(* Logix 5000 project; controller DNP3Master vendor 1 type 14 code 96 rev 19.13; software revision 19.01; part 3 of 5 *)

ADD_ON_INSTRUCTION PSDNP3EventG21V05   (* revision 1.0, vendor ProSoft Technology Inc *)
// Processes DNP3 Event and updates corresponding static DNP3 object. (Report by Exception.)
// G21V05 - Frozen Counter - 32bit with Status and Time
VAR_IN_OUT
   EventBuffer : PSDNP3MasterEvent[1]; {required}
END_VAR
VAR_INPUT
   BufferSize : DINT; {required}
   CurrentBufferIndex : DINT; {required}
   Reset : BOOL; {required}
   OutstationNodeAddress : INT; {required}
   OutstationIPAddress0 : INT; {required}
   OutstationIPAddress1 : INT; {required}
   OutstationIPAddress2 : INT; {required}
   OutstationIPAddress3 : INT; {required}
END_VAR
VAR_IN_OUT
   DNP3StaticObject : PSDNP3FrozenCounter32WithFlagTime[1]; {required}
END_VAR
VAR_INPUT
   MaxtElementCount : DINT; {required}
END_VAR
VAR_OUTPUT
   EventsProcessed : DINT; {access Read Only, visible}
   LastElementIndex : DINT; {access Read Only, visible}
   LastValue : DINT; {access Read Only, visible}
   LastStatus : SINT; {access Read Only, visible}
   CurrentUnloadIndex : DINT; {access Read Only, visible}
END_VAR
VAR
   UnloadIndex : DINT; {access None}
   EnableInTemp : BOOL; {access None}
   InitialScan : BOOL; {access None}
   EntryValidForProcessing : BOOL; {access None}
   ElementIndex : DINT; {access None}
   NextIndex : DINT; {access None}
   ResetPulse : BOOL; {access None}
   ResetONS : BOOL; {access None}
END_VAR

ROUTINE Logic   (* ladder *)
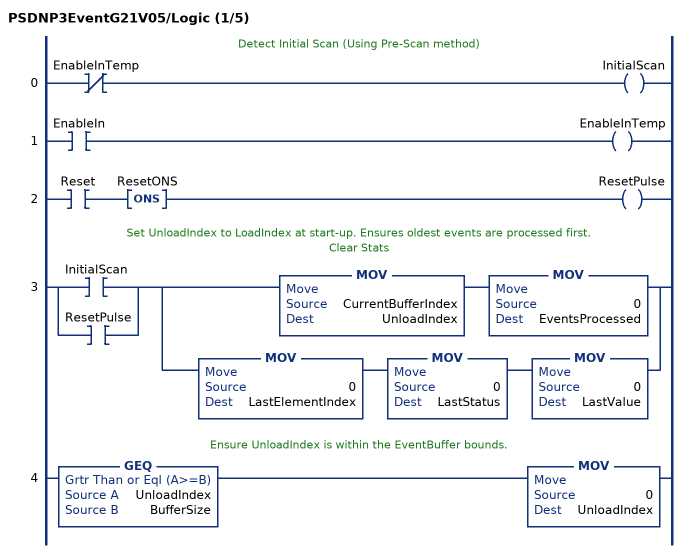
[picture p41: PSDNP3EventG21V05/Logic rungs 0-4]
   // Detect Initial Scan (Using Pre-Scan method)
   0: XIO(EnableInTemp)OTE(InitialScan);
   1: XIC(EnableIn)OTE(EnableInTemp);
   2: XIC(Reset)ONS(ResetONS)OTE(ResetPulse);
   // Set UnloadIndex to LoadIndex at start-up. Ensures oldest events are processed first.
   // Clear Stats
   3: [XIC(InitialScan) ,XIC(ResetPulse) ][MOV(CurrentBufferIndex,UnloadIndex) MOV(0,EventsProcessed) ,MOV(0,LastElementIndex) MOV(0,LastStatus) MOV(0,LastValue) ];
   // Ensure UnloadIndex is within the EventBuffer bounds.
   4: GEQ(UnloadIndex,BufferSize)MOV(0,UnloadIndex);
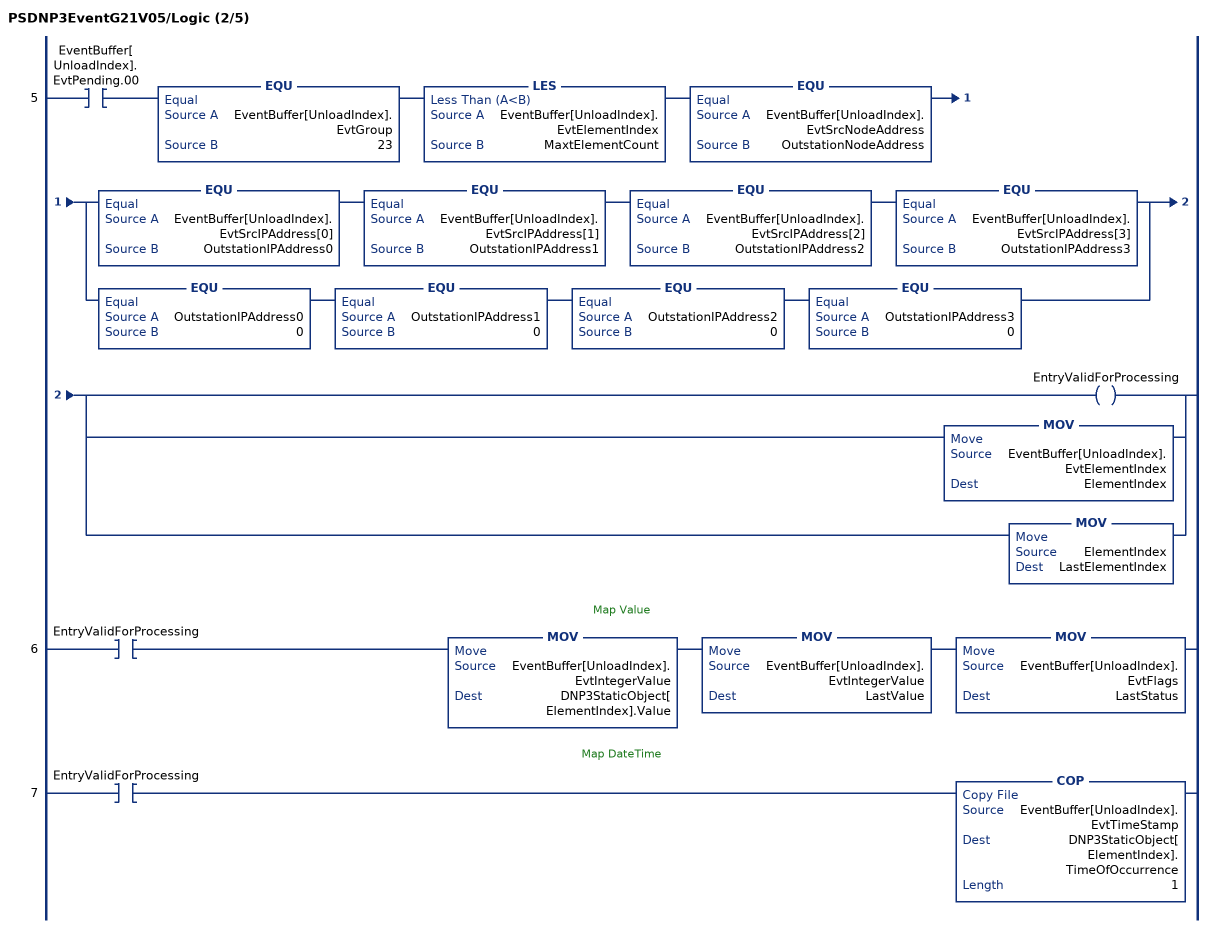
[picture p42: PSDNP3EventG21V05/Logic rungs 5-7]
   5: XIC(EventBuffer[UnloadIndex].EvtPending.00)EQU(EventBuffer[UnloadIndex].EvtGroup,23)LES(EventBuffer[UnloadIndex].EvtElementIndex,MaxtElementCount)EQU(EventBuffer[UnloadIndex].EvtSrcNodeAddress,OutstationNodeAddress)[EQU(EventBuffer[UnloadIndex].EvtSrcIPAddress[0],OutstationIPAddress0) EQU(EventBuffer[UnloadIndex].EvtSrcIPAddress[1],OutstationIPAddress1) EQU(EventBuffer[UnloadIndex].EvtSrcIPAddress[2],OutstationIPAddress2) EQU(EventBuffer[UnloadIndex].EvtSrcIPAddress[3],OutstationIPAddress3) ,EQU(OutstationIPAddress0,0) EQU(OutstationIPAddress1,0) EQU(OutstationIPAddress2,0) EQU(OutstationIPAddress3,0) ][OTE(EntryValidForProcessing) ,MOV(EventBuffer[UnloadIndex].EvtElementIndex,ElementIndex) ,MOV(ElementIndex,LastElementIndex) ];
   // Map Value
   6: XIC(EntryValidForProcessing)MOV(EventBuffer[UnloadIndex].EvtIntegerValue,DNP3StaticObject[ElementIndex].Value)MOV(EventBuffer[UnloadIndex].EvtIntegerValue,LastValue)MOV(EventBuffer[UnloadIndex].EvtFlags,LastStatus);
   // Map DateTime
   7: XIC(EntryValidForProcessing)COP(EventBuffer[UnloadIndex].EvtTimeStamp,DNP3StaticObject[ElementIndex].TimeOfOccurrence,1);
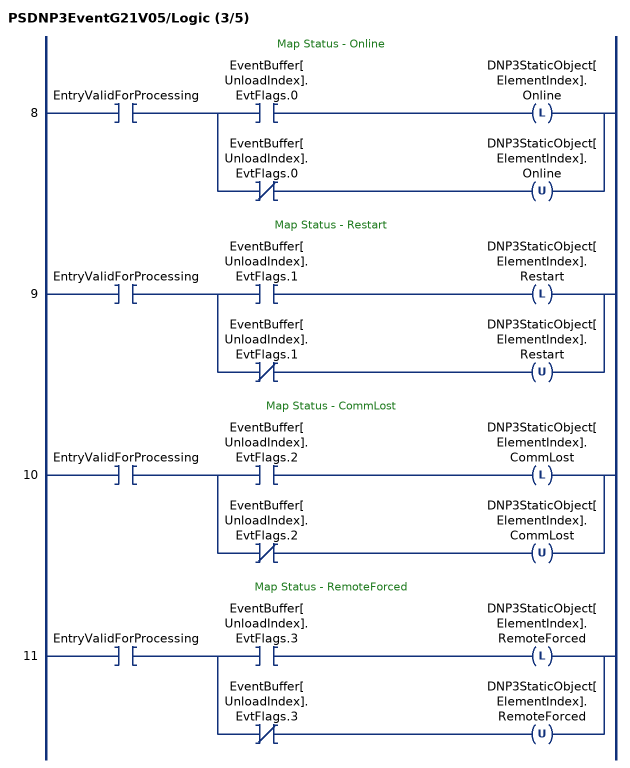
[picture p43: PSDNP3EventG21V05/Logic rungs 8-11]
   // Map Status - Online
   8: XIC(EntryValidForProcessing)[XIC(EventBuffer[UnloadIndex].EvtFlags.0) OTL(DNP3StaticObject[ElementIndex].Online) ,XIO(EventBuffer[UnloadIndex].EvtFlags.0) OTU(DNP3StaticObject[ElementIndex].Online) ];
   // Map Status - Restart
   9: XIC(EntryValidForProcessing)[XIC(EventBuffer[UnloadIndex].EvtFlags.1) OTL(DNP3StaticObject[ElementIndex].Restart) ,XIO(EventBuffer[UnloadIndex].EvtFlags.1) OTU(DNP3StaticObject[ElementIndex].Restart) ];
   // Map Status - CommLost
   10: XIC(EntryValidForProcessing)[XIC(EventBuffer[UnloadIndex].EvtFlags.2) OTL(DNP3StaticObject[ElementIndex].CommLost) ,XIO(EventBuffer[UnloadIndex].EvtFlags.2) OTU(DNP3StaticObject[ElementIndex].CommLost) ];
   // Map Status - RemoteForced
   11: XIC(EntryValidForProcessing)[XIC(EventBuffer[UnloadIndex].EvtFlags.3) OTL(DNP3StaticObject[ElementIndex].RemoteForced) ,XIO(EventBuffer[UnloadIndex].EvtFlags.3) OTU(DNP3StaticObject[ElementIndex].RemoteForced) ];
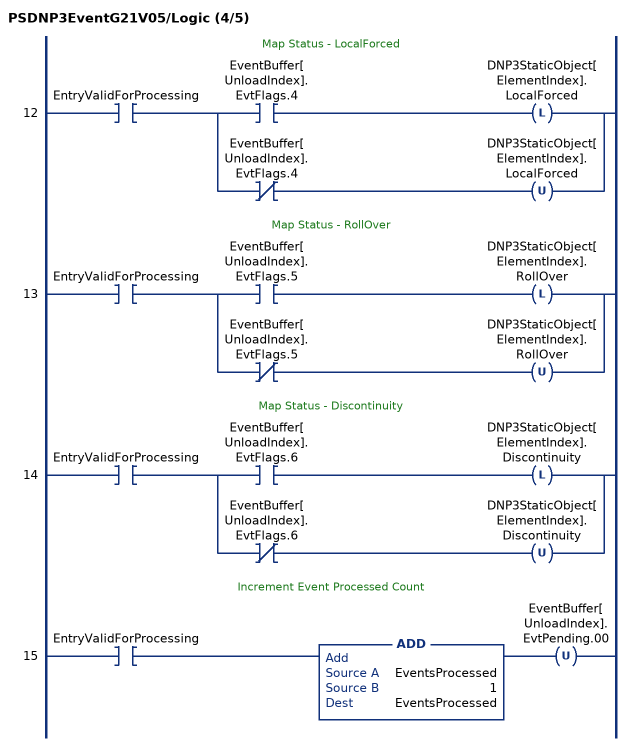
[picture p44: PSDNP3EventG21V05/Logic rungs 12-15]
   // Map Status - LocalForced
   12: XIC(EntryValidForProcessing)[XIC(EventBuffer[UnloadIndex].EvtFlags.4) OTL(DNP3StaticObject[ElementIndex].LocalForced) ,XIO(EventBuffer[UnloadIndex].EvtFlags.4) OTU(DNP3StaticObject[ElementIndex].LocalForced) ];
   // Map Status - RollOver
   13: XIC(EntryValidForProcessing)[XIC(EventBuffer[UnloadIndex].EvtFlags.5) OTL(DNP3StaticObject[ElementIndex].RollOver) ,XIO(EventBuffer[UnloadIndex].EvtFlags.5) OTU(DNP3StaticObject[ElementIndex].RollOver) ];
   // Map Status - Discontinuity
   14: XIC(EntryValidForProcessing)[XIC(EventBuffer[UnloadIndex].EvtFlags.6) OTL(DNP3StaticObject[ElementIndex].Discontinuity) ,XIO(EventBuffer[UnloadIndex].EvtFlags.6) OTU(DNP3StaticObject[ElementIndex].Discontinuity) ];
   // Increment Event Processed Count
   15: XIC(EntryValidForProcessing)ADD(EventsProcessed,1,EventsProcessed)OTU(EventBuffer[UnloadIndex].EvtPending.00);
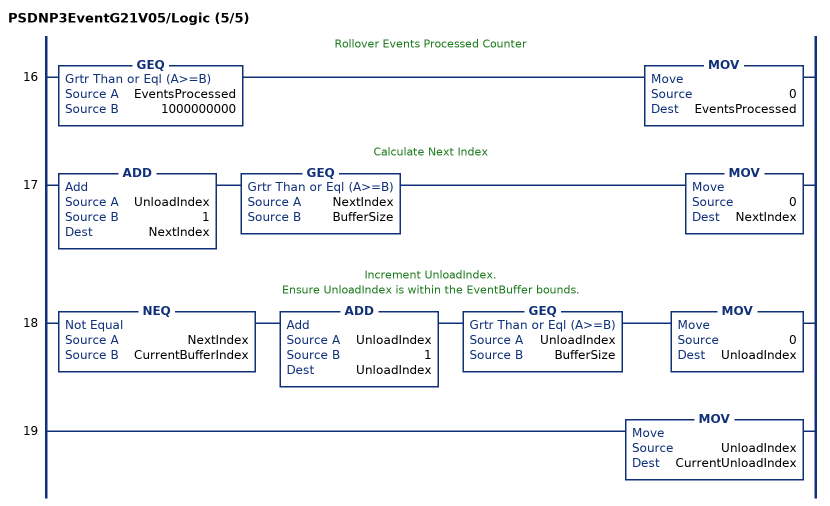
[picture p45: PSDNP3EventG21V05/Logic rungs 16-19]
   // Rollover Events Processed Counter
   16: GEQ(EventsProcessed,1000000000)MOV(0,EventsProcessed);
   // Calculate Next Index
   17: ADD(UnloadIndex,1,NextIndex)GEQ(NextIndex,BufferSize)MOV(0,NextIndex);
   // Increment UnloadIndex.
   // Ensure UnloadIndex is within the EventBuffer bounds.
   18: NEQ(NextIndex,CurrentBufferIndex)ADD(UnloadIndex,1,UnloadIndex)GEQ(UnloadIndex,BufferSize)MOV(0,UnloadIndex);
   19: MOV(UnloadIndex,CurrentUnloadIndex);
END_ROUTINE
END_ADD_ON_INSTRUCTION

ADD_ON_INSTRUCTION PSDNP3EventG21V06   (* revision 1.0, vendor ProSoft Technology Inc *)
// Processes DNP3 Event and updates corresponding static DNP3 object. (Report by Exception.)
// G21V06 - Frozen Counter - 16bit with Status and Time
VAR_IN_OUT
   EventBuffer : PSDNP3MasterEvent[1]; {required}
END_VAR
VAR_INPUT
   BufferSize : DINT; {required}
   CurrentBufferIndex : DINT; {required}
   Reset : BOOL; {required}
   OutstationNodeAddress : INT; {required}
   OutstationIPAddress0 : INT; {required}
   OutstationIPAddress1 : INT; {required}
   OutstationIPAddress2 : INT; {required}
   OutstationIPAddress3 : INT; {required}
END_VAR
VAR_IN_OUT
   DNP3StaticObject : PSDNP3FrozenCounter16WithFlagTime[1]; {required}
END_VAR
VAR_INPUT
   MaxtElementCount : DINT; {required}
END_VAR
VAR_OUTPUT
   EventsProcessed : DINT; {access Read Only, visible}
   LastElementIndex : DINT; {access Read Only, visible}
   LastValue : DINT; {access Read Only, visible}
   LastStatus : SINT; {access Read Only, visible}
   CurrentUnloadIndex : DINT; {access Read Only, visible}
END_VAR
VAR
   UnloadIndex : DINT; {access None}
   EnableInTemp : BOOL; {access None}
   InitialScan : BOOL; {access None}
   EntryValidForProcessing : BOOL; {access None}
   ElementIndex : DINT; {access None}
   NextIndex : DINT; {access None}
   ResetPulse : BOOL; {access None}
   ResetONS : BOOL; {access None}
END_VAR

ROUTINE Logic   (* ladder *)
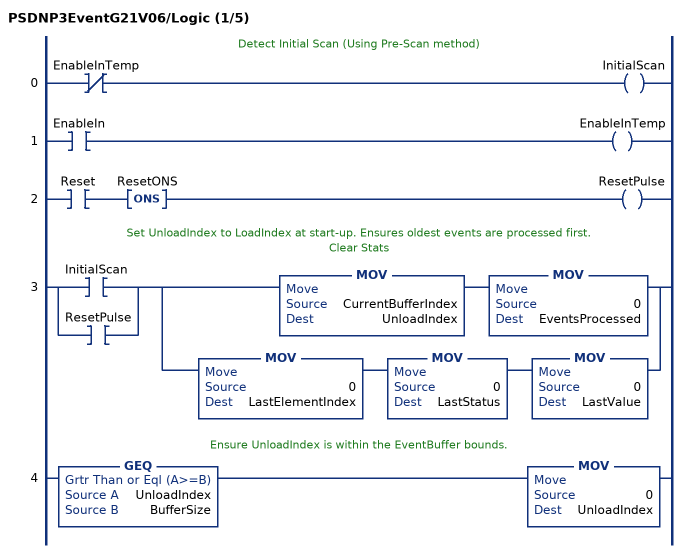
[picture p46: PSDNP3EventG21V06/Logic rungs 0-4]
   // Detect Initial Scan (Using Pre-Scan method)
   0: XIO(EnableInTemp)OTE(InitialScan);
   1: XIC(EnableIn)OTE(EnableInTemp);
   2: XIC(Reset)ONS(ResetONS)OTE(ResetPulse);
   // Set UnloadIndex to LoadIndex at start-up. Ensures oldest events are processed first.
   // Clear Stats
   3: [XIC(InitialScan) ,XIC(ResetPulse) ][MOV(CurrentBufferIndex,UnloadIndex) MOV(0,EventsProcessed) ,MOV(0,LastElementIndex) MOV(0,LastStatus) MOV(0,LastValue) ];
   // Ensure UnloadIndex is within the EventBuffer bounds.
   4: GEQ(UnloadIndex,BufferSize)MOV(0,UnloadIndex);
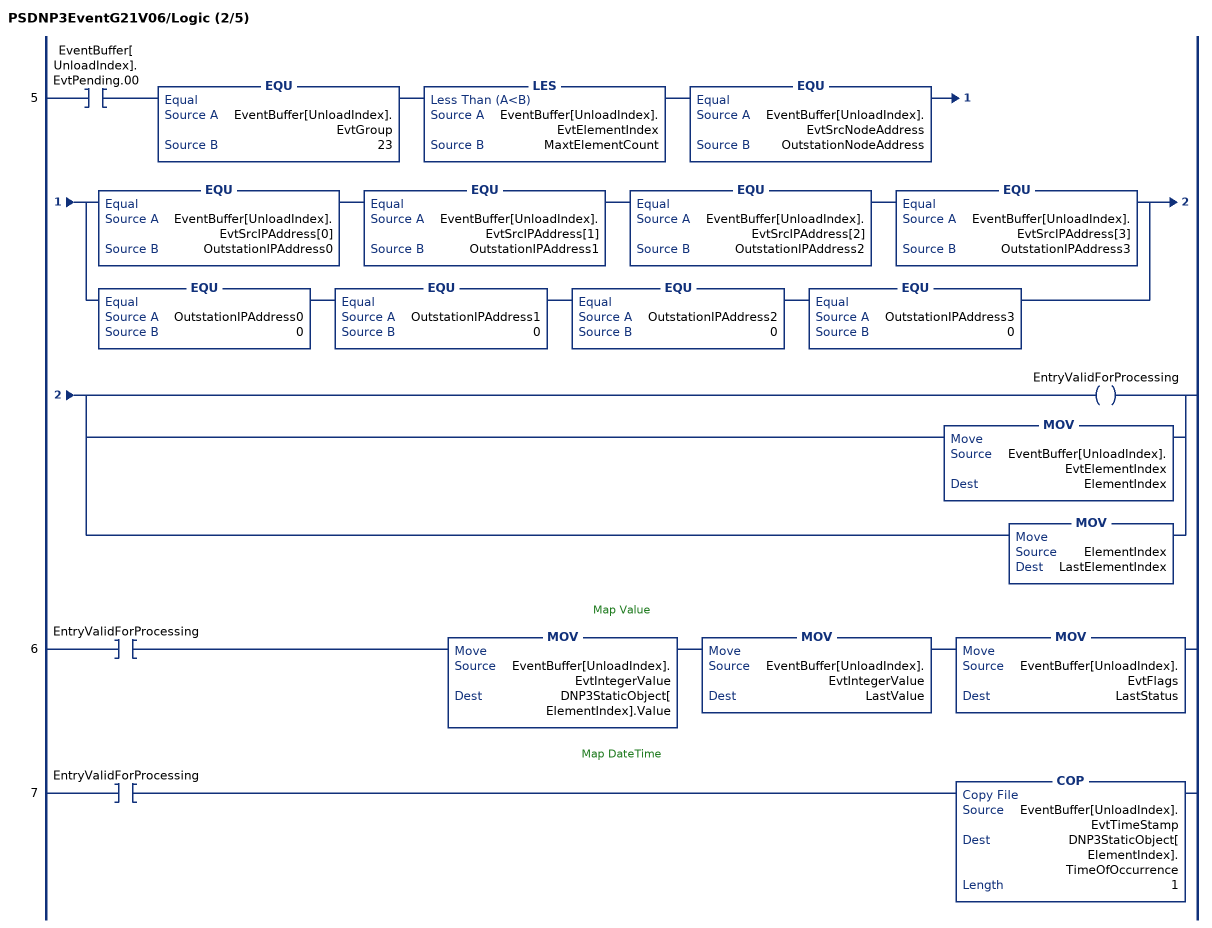
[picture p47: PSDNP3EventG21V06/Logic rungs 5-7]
   5: XIC(EventBuffer[UnloadIndex].EvtPending.00)EQU(EventBuffer[UnloadIndex].EvtGroup,23)LES(EventBuffer[UnloadIndex].EvtElementIndex,MaxtElementCount)EQU(EventBuffer[UnloadIndex].EvtSrcNodeAddress,OutstationNodeAddress)[EQU(EventBuffer[UnloadIndex].EvtSrcIPAddress[0],OutstationIPAddress0) EQU(EventBuffer[UnloadIndex].EvtSrcIPAddress[1],OutstationIPAddress1) EQU(EventBuffer[UnloadIndex].EvtSrcIPAddress[2],OutstationIPAddress2) EQU(EventBuffer[UnloadIndex].EvtSrcIPAddress[3],OutstationIPAddress3) ,EQU(OutstationIPAddress0,0) EQU(OutstationIPAddress1,0) EQU(OutstationIPAddress2,0) EQU(OutstationIPAddress3,0) ][OTE(EntryValidForProcessing) ,MOV(EventBuffer[UnloadIndex].EvtElementIndex,ElementIndex) ,MOV(ElementIndex,LastElementIndex) ];
   // Map Value
   6: XIC(EntryValidForProcessing)MOV(EventBuffer[UnloadIndex].EvtIntegerValue,DNP3StaticObject[ElementIndex].Value)MOV(EventBuffer[UnloadIndex].EvtIntegerValue,LastValue)MOV(EventBuffer[UnloadIndex].EvtFlags,LastStatus);
   // Map DateTime
   7: XIC(EntryValidForProcessing)COP(EventBuffer[UnloadIndex].EvtTimeStamp,DNP3StaticObject[ElementIndex].TimeOfOccurrence,1);
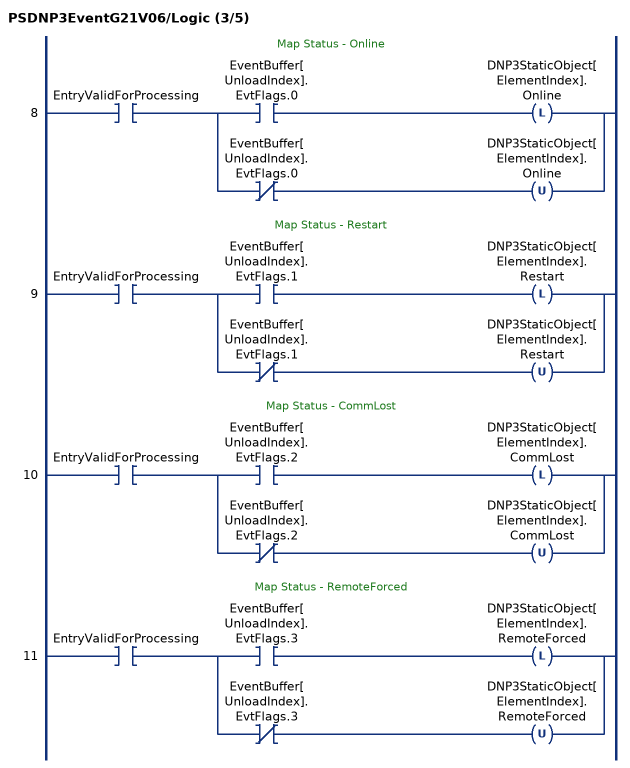
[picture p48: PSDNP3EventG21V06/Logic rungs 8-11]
   // Map Status - Online
   8: XIC(EntryValidForProcessing)[XIC(EventBuffer[UnloadIndex].EvtFlags.0) OTL(DNP3StaticObject[ElementIndex].Online) ,XIO(EventBuffer[UnloadIndex].EvtFlags.0) OTU(DNP3StaticObject[ElementIndex].Online) ];
   // Map Status - Restart
   9: XIC(EntryValidForProcessing)[XIC(EventBuffer[UnloadIndex].EvtFlags.1) OTL(DNP3StaticObject[ElementIndex].Restart) ,XIO(EventBuffer[UnloadIndex].EvtFlags.1) OTU(DNP3StaticObject[ElementIndex].Restart) ];
   // Map Status - CommLost
   10: XIC(EntryValidForProcessing)[XIC(EventBuffer[UnloadIndex].EvtFlags.2) OTL(DNP3StaticObject[ElementIndex].CommLost) ,XIO(EventBuffer[UnloadIndex].EvtFlags.2) OTU(DNP3StaticObject[ElementIndex].CommLost) ];
   // Map Status - RemoteForced
   11: XIC(EntryValidForProcessing)[XIC(EventBuffer[UnloadIndex].EvtFlags.3) OTL(DNP3StaticObject[ElementIndex].RemoteForced) ,XIO(EventBuffer[UnloadIndex].EvtFlags.3) OTU(DNP3StaticObject[ElementIndex].RemoteForced) ];
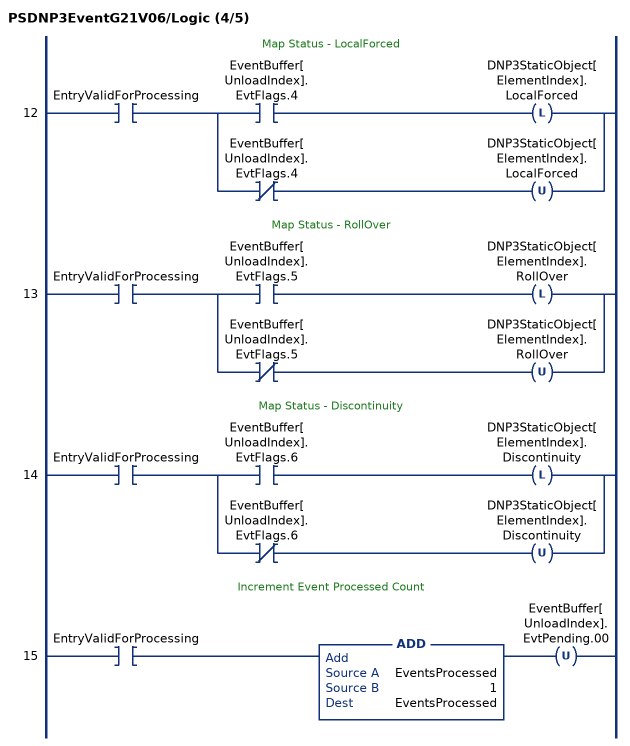
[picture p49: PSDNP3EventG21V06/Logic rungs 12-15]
   // Map Status - LocalForced
   12: XIC(EntryValidForProcessing)[XIC(EventBuffer[UnloadIndex].EvtFlags.4) OTL(DNP3StaticObject[ElementIndex].LocalForced) ,XIO(EventBuffer[UnloadIndex].EvtFlags.4) OTU(DNP3StaticObject[ElementIndex].LocalForced) ];
   // Map Status - RollOver
   13: XIC(EntryValidForProcessing)[XIC(EventBuffer[UnloadIndex].EvtFlags.5) OTL(DNP3StaticObject[ElementIndex].RollOver) ,XIO(EventBuffer[UnloadIndex].EvtFlags.5) OTU(DNP3StaticObject[ElementIndex].RollOver) ];
   // Map Status - Discontinuity
   14: XIC(EntryValidForProcessing)[XIC(EventBuffer[UnloadIndex].EvtFlags.6) OTL(DNP3StaticObject[ElementIndex].Discontinuity) ,XIO(EventBuffer[UnloadIndex].EvtFlags.6) OTU(DNP3StaticObject[ElementIndex].Discontinuity) ];
   // Increment Event Processed Count
   15: XIC(EntryValidForProcessing)ADD(EventsProcessed,1,EventsProcessed)OTU(EventBuffer[UnloadIndex].EvtPending.00);
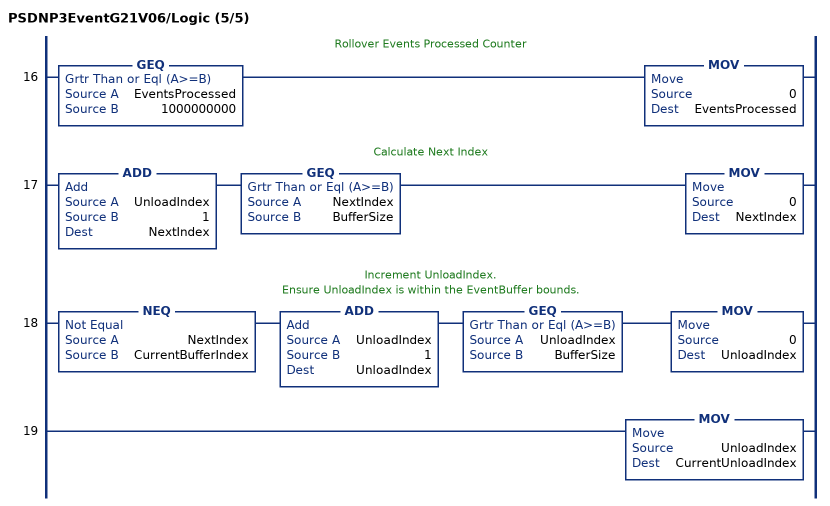
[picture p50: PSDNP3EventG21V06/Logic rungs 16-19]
   // Rollover Events Processed Counter
   16: GEQ(EventsProcessed,1000000000)MOV(0,EventsProcessed);
   // Calculate Next Index
   17: ADD(UnloadIndex,1,NextIndex)GEQ(NextIndex,BufferSize)MOV(0,NextIndex);
   // Increment UnloadIndex.
   // Ensure UnloadIndex is within the EventBuffer bounds.
   18: NEQ(NextIndex,CurrentBufferIndex)ADD(UnloadIndex,1,UnloadIndex)GEQ(UnloadIndex,BufferSize)MOV(0,UnloadIndex);
   19: MOV(UnloadIndex,CurrentUnloadIndex);
END_ROUTINE
END_ADD_ON_INSTRUCTION

ADD_ON_INSTRUCTION PSDNP3EventG21V09   (* revision 1.0, vendor ProSoft Technology Inc *)
// Processes DNP3 Event and updates corresponding static DNP3 object. (Report by Exception.)
// G21V09 - Frozen Counter - 32bit no Status
VAR_IN_OUT
   EventBuffer : PSDNP3MasterEvent[1]; {required}
END_VAR
VAR_INPUT
   BufferSize : DINT; {required}
   CurrentBufferIndex : DINT; {required}
   Reset : BOOL; {required}
   OutstationNodeAddress : INT; {required}
   OutstationIPAddress0 : INT; {required}
   OutstationIPAddress1 : INT; {required}
   OutstationIPAddress2 : INT; {required}
   OutstationIPAddress3 : INT; {required}
END_VAR
VAR_IN_OUT
   DNP3StaticObject : DINT[1]; {required}
END_VAR
VAR_INPUT
   MaxtElementCount : DINT; {required}
END_VAR
VAR_OUTPUT
   EventsProcessed : DINT; {access Read Only, visible}
   LastElementIndex : DINT; {access Read Only, visible}
   LastValue : DINT; {access Read Only, visible}
   LastStatus : SINT; {access Read Only, visible}
   CurrentUnloadIndex : DINT; {access Read Only, visible}
END_VAR
VAR
   UnloadIndex : DINT; {access None}
   EnableInTemp : BOOL; {access None}
   InitialScan : BOOL; {access None}
   EntryValidForProcessing : BOOL; {access None}
   ElementIndex : DINT; {access None}
   NextIndex : DINT; {access None}
   ResetPulse : BOOL; {access None}
   ResetONS : BOOL; {access None}
END_VAR

ROUTINE Logic   (* ladder *)
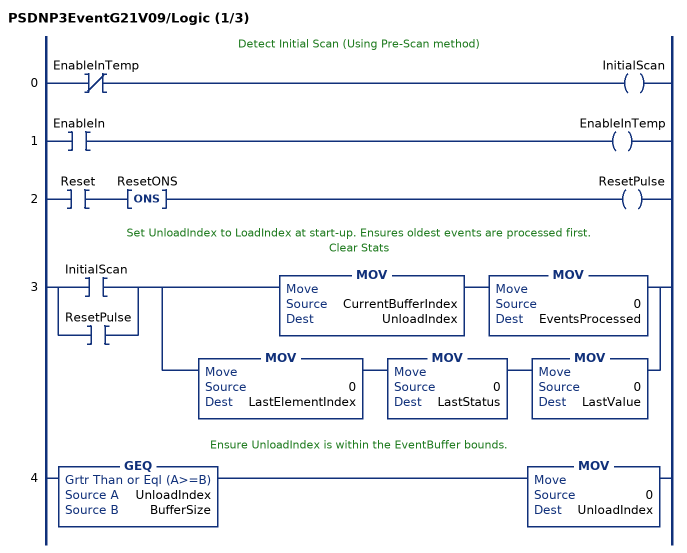
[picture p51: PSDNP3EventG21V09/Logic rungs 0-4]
   // Detect Initial Scan (Using Pre-Scan method)
   0: XIO(EnableInTemp)OTE(InitialScan);
   1: XIC(EnableIn)OTE(EnableInTemp);
   2: XIC(Reset)ONS(ResetONS)OTE(ResetPulse);
   // Set UnloadIndex to LoadIndex at start-up. Ensures oldest events are processed first.
   // Clear Stats
   3: [XIC(InitialScan) ,XIC(ResetPulse) ][MOV(CurrentBufferIndex,UnloadIndex) MOV(0,EventsProcessed) ,MOV(0,LastElementIndex) MOV(0,LastStatus) MOV(0,LastValue) ];
   // Ensure UnloadIndex is within the EventBuffer bounds.
   4: GEQ(UnloadIndex,BufferSize)MOV(0,UnloadIndex);
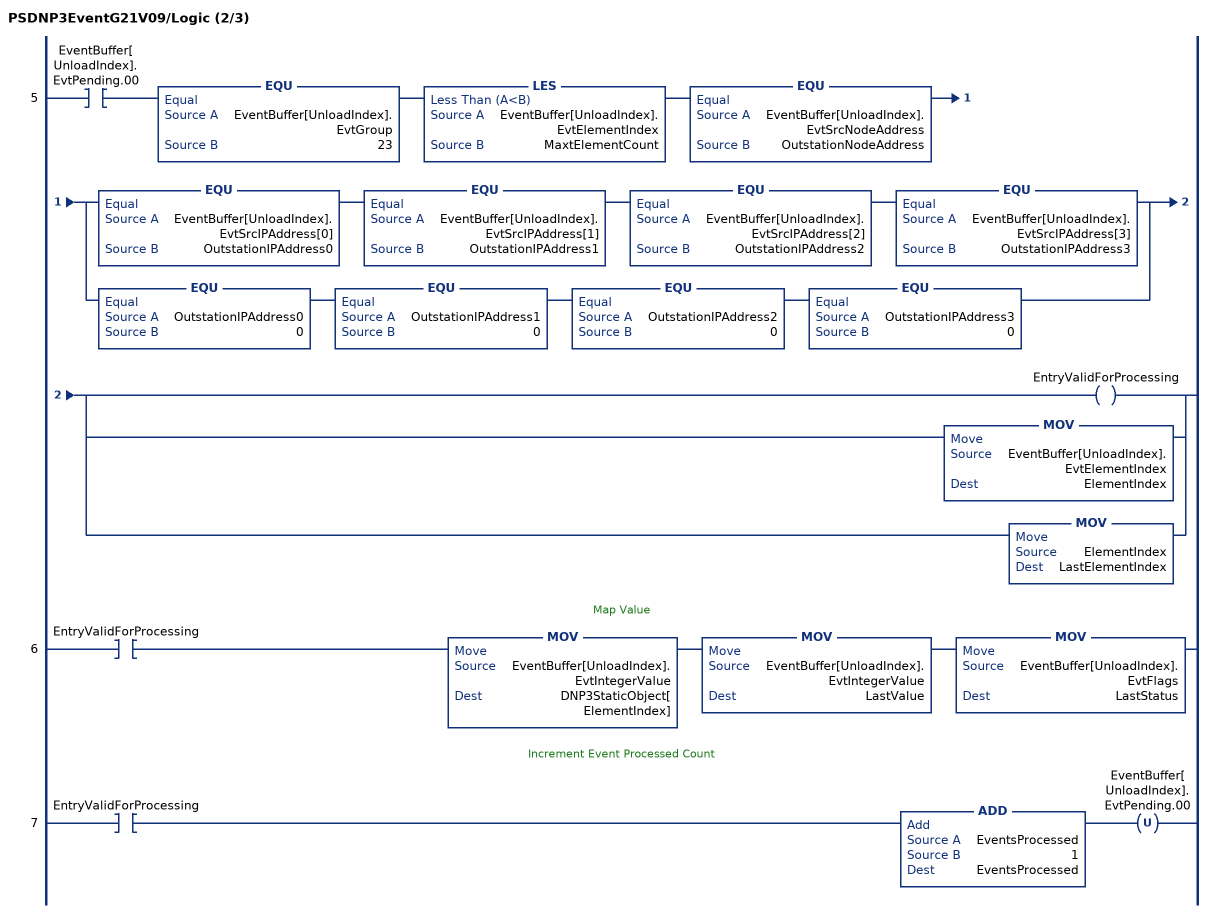
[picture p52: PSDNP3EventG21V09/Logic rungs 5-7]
   5: XIC(EventBuffer[UnloadIndex].EvtPending.00)EQU(EventBuffer[UnloadIndex].EvtGroup,23)LES(EventBuffer[UnloadIndex].EvtElementIndex,MaxtElementCount)EQU(EventBuffer[UnloadIndex].EvtSrcNodeAddress,OutstationNodeAddress)[EQU(EventBuffer[UnloadIndex].EvtSrcIPAddress[0],OutstationIPAddress0) EQU(EventBuffer[UnloadIndex].EvtSrcIPAddress[1],OutstationIPAddress1) EQU(EventBuffer[UnloadIndex].EvtSrcIPAddress[2],OutstationIPAddress2) EQU(EventBuffer[UnloadIndex].EvtSrcIPAddress[3],OutstationIPAddress3) ,EQU(OutstationIPAddress0,0) EQU(OutstationIPAddress1,0) EQU(OutstationIPAddress2,0) EQU(OutstationIPAddress3,0) ][OTE(EntryValidForProcessing) ,MOV(EventBuffer[UnloadIndex].EvtElementIndex,ElementIndex) ,MOV(ElementIndex,LastElementIndex) ];
   // Map Value
   6: XIC(EntryValidForProcessing)MOV(EventBuffer[UnloadIndex].EvtIntegerValue,DNP3StaticObject[ElementIndex])MOV(EventBuffer[UnloadIndex].EvtIntegerValue,LastValue)MOV(EventBuffer[UnloadIndex].EvtFlags,LastStatus);
   // Increment Event Processed Count
   7: XIC(EntryValidForProcessing)ADD(EventsProcessed,1,EventsProcessed)OTU(EventBuffer[UnloadIndex].EvtPending.00);
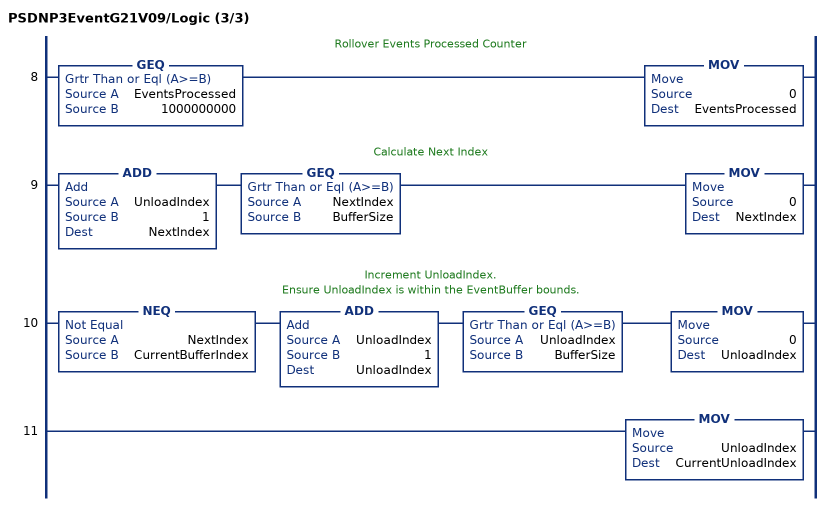
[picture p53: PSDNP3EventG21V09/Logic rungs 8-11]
   // Rollover Events Processed Counter
   8: GEQ(EventsProcessed,1000000000)MOV(0,EventsProcessed);
   // Calculate Next Index
   9: ADD(UnloadIndex,1,NextIndex)GEQ(NextIndex,BufferSize)MOV(0,NextIndex);
   // Increment UnloadIndex.
   // Ensure UnloadIndex is within the EventBuffer bounds.
   10: NEQ(NextIndex,CurrentBufferIndex)ADD(UnloadIndex,1,UnloadIndex)GEQ(UnloadIndex,BufferSize)MOV(0,UnloadIndex);
   11: MOV(UnloadIndex,CurrentUnloadIndex);
END_ROUTINE
END_ADD_ON_INSTRUCTION

ADD_ON_INSTRUCTION PSDNP3EventG21V10   (* revision 1.0, vendor ProSoft Technology Inc *)
// Processes DNP3 Event and updates corresponding static DNP3 object. (Report by Exception.)
// G21V10 - Frozen Counter - 16bit no Status
VAR_IN_OUT
   EventBuffer : PSDNP3MasterEvent[1]; {required}
END_VAR
VAR_INPUT
   BufferSize : DINT; {required}
   CurrentBufferIndex : DINT; {required}
   Reset : BOOL; {required}
   OutstationNodeAddress : INT; {required}
   OutstationIPAddress0 : INT; {required}
   OutstationIPAddress1 : INT; {required}
   OutstationIPAddress2 : INT; {required}
   OutstationIPAddress3 : INT; {required}
END_VAR
VAR_IN_OUT
   DNP3StaticObject : INT[1]; {required}
END_VAR
VAR_INPUT
   MaxtElementCount : DINT; {required}
END_VAR
VAR_OUTPUT
   EventsProcessed : DINT; {access Read Only, visible}
   LastElementIndex : DINT; {access Read Only, visible}
   LastValue : DINT; {access Read Only, visible}
   LastStatus : SINT; {access Read Only, visible}
   CurrentUnloadIndex : DINT; {access Read Only, visible}
END_VAR
VAR
   UnloadIndex : DINT; {access None}
   EnableInTemp : BOOL; {access None}
   InitialScan : BOOL; {access None}
   EntryValidForProcessing : BOOL; {access None}
   ElementIndex : DINT; {access None}
   NextIndex : DINT; {access None}
   ResetPulse : BOOL; {access None}
   ResetONS : BOOL; {access None}
END_VAR

ROUTINE Logic   (* ladder *)
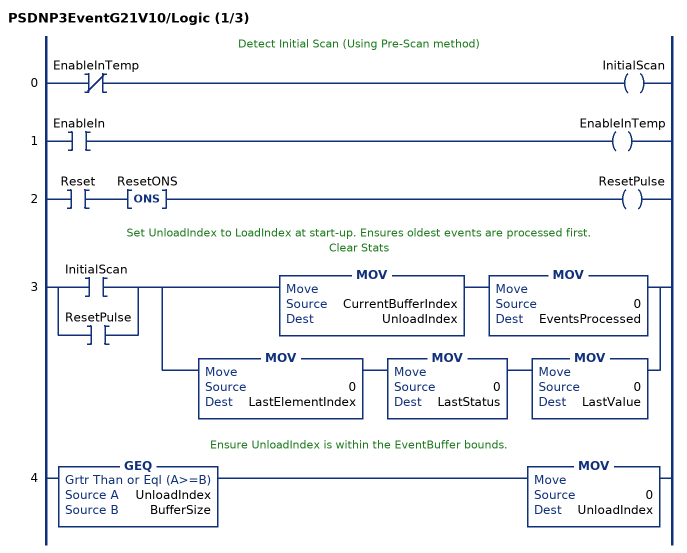
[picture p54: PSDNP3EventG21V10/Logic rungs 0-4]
   // Detect Initial Scan (Using Pre-Scan method)
   0: XIO(EnableInTemp)OTE(InitialScan);
   1: XIC(EnableIn)OTE(EnableInTemp);
   2: XIC(Reset)ONS(ResetONS)OTE(ResetPulse);
   // Set UnloadIndex to LoadIndex at start-up. Ensures oldest events are processed first.
   // Clear Stats
   3: [XIC(InitialScan) ,XIC(ResetPulse) ][MOV(CurrentBufferIndex,UnloadIndex) MOV(0,EventsProcessed) ,MOV(0,LastElementIndex) MOV(0,LastStatus) MOV(0,LastValue) ];
   // Ensure UnloadIndex is within the EventBuffer bounds.
   4: GEQ(UnloadIndex,BufferSize)MOV(0,UnloadIndex);
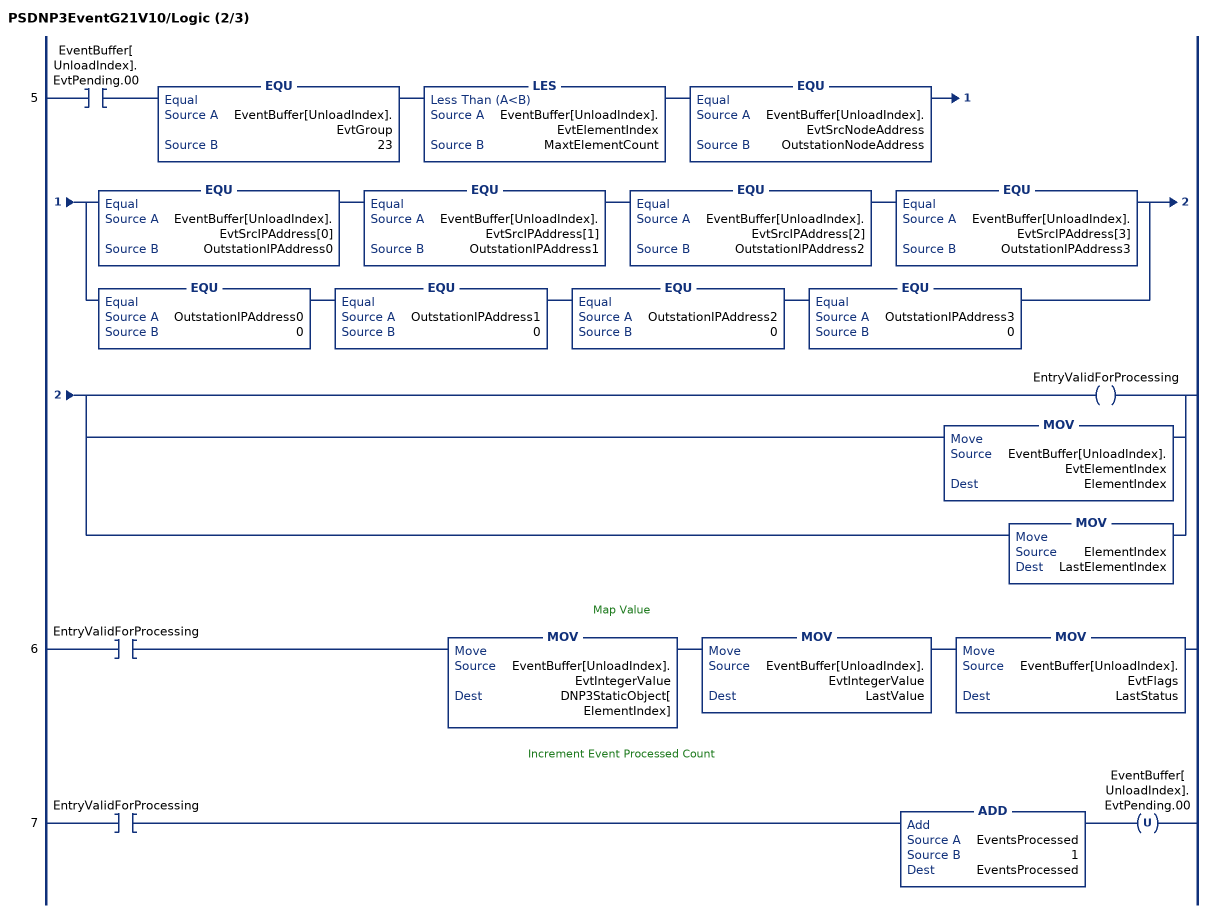
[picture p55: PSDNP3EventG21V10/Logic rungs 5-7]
   5: XIC(EventBuffer[UnloadIndex].EvtPending.00)EQU(EventBuffer[UnloadIndex].EvtGroup,23)LES(EventBuffer[UnloadIndex].EvtElementIndex,MaxtElementCount)EQU(EventBuffer[UnloadIndex].EvtSrcNodeAddress,OutstationNodeAddress)[EQU(EventBuffer[UnloadIndex].EvtSrcIPAddress[0],OutstationIPAddress0) EQU(EventBuffer[UnloadIndex].EvtSrcIPAddress[1],OutstationIPAddress1) EQU(EventBuffer[UnloadIndex].EvtSrcIPAddress[2],OutstationIPAddress2) EQU(EventBuffer[UnloadIndex].EvtSrcIPAddress[3],OutstationIPAddress3) ,EQU(OutstationIPAddress0,0) EQU(OutstationIPAddress1,0) EQU(OutstationIPAddress2,0) EQU(OutstationIPAddress3,0) ][OTE(EntryValidForProcessing) ,MOV(EventBuffer[UnloadIndex].EvtElementIndex,ElementIndex) ,MOV(ElementIndex,LastElementIndex) ];
   // Map Value
   6: XIC(EntryValidForProcessing)MOV(EventBuffer[UnloadIndex].EvtIntegerValue,DNP3StaticObject[ElementIndex])MOV(EventBuffer[UnloadIndex].EvtIntegerValue,LastValue)MOV(EventBuffer[UnloadIndex].EvtFlags,LastStatus);
   // Increment Event Processed Count
   7: XIC(EntryValidForProcessing)ADD(EventsProcessed,1,EventsProcessed)OTU(EventBuffer[UnloadIndex].EvtPending.00);
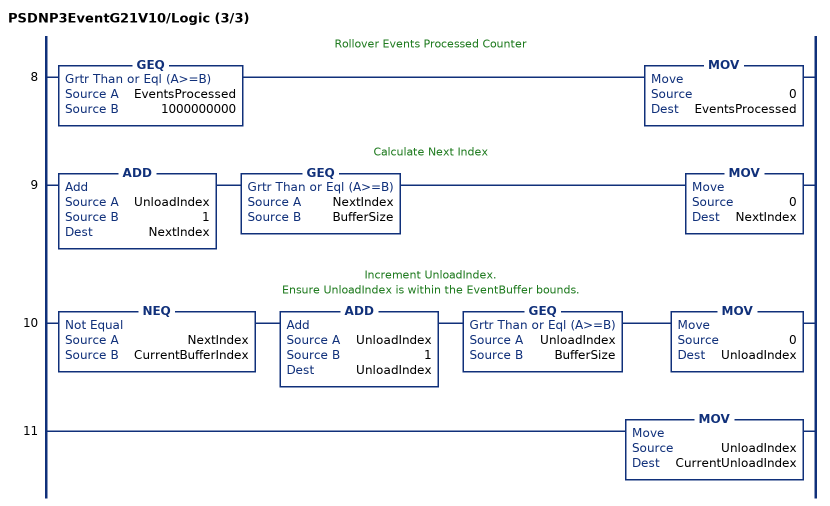
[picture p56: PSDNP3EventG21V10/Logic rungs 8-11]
   // Rollover Events Processed Counter
   8: GEQ(EventsProcessed,1000000000)MOV(0,EventsProcessed);
   // Calculate Next Index
   9: ADD(UnloadIndex,1,NextIndex)GEQ(NextIndex,BufferSize)MOV(0,NextIndex);
   // Increment UnloadIndex.
   // Ensure UnloadIndex is within the EventBuffer bounds.
   10: NEQ(NextIndex,CurrentBufferIndex)ADD(UnloadIndex,1,UnloadIndex)GEQ(UnloadIndex,BufferSize)MOV(0,UnloadIndex);
   11: MOV(UnloadIndex,CurrentUnloadIndex);
END_ROUTINE
END_ADD_ON_INSTRUCTION

ADD_ON_INSTRUCTION PSDNP3EventG30V01   (* revision 1.0, vendor ProSoft Technology Inc *)
// Processes DNP3 Event and updates corresponding static DNP3 object. (Report by Exception.)
// G30V01 - Analog Input - 32bit with Status
VAR_IN_OUT
   EventBuffer : PSDNP3MasterEvent[1]; {required}
END_VAR
VAR_INPUT
   BufferSize : DINT; {required}
   CurrentBufferIndex : DINT; {required}
   Reset : BOOL; {required}
   OutstationNodeAddress : INT; {required}
   OutstationIPAddress0 : INT; {required}
   OutstationIPAddress1 : INT; {required}
   OutstationIPAddress2 : INT; {required}
   OutstationIPAddress3 : INT; {required}
END_VAR
VAR_IN_OUT
   DNP3StaticObject : PSDNP3AnalogInput32Flag[1]; {required}
END_VAR
VAR_INPUT
   MaxtElementCount : DINT; {required}
END_VAR
VAR_OUTPUT
   EventsProcessed : DINT; {access Read Only, visible}
   LastElementIndex : DINT; {access Read Only, visible}
   LastValue : DINT; {access Read Only, visible}
   LastStatus : SINT; {access Read Only, visible}
   CurrentUnloadIndex : DINT; {access Read Only, visible}
END_VAR
VAR
   UnloadIndex : DINT; {access None}
   EnableInTemp : BOOL; {access None}
   InitialScan : BOOL; {access None}
   EntryValidForProcessing : BOOL; {access None}
   ElementIndex : DINT; {access None}
   NextIndex : DINT; {access None}
   ResetPulse : BOOL; {access None}
   ResetONS : BOOL; {access None}
END_VAR

ROUTINE Logic   (* ladder *)
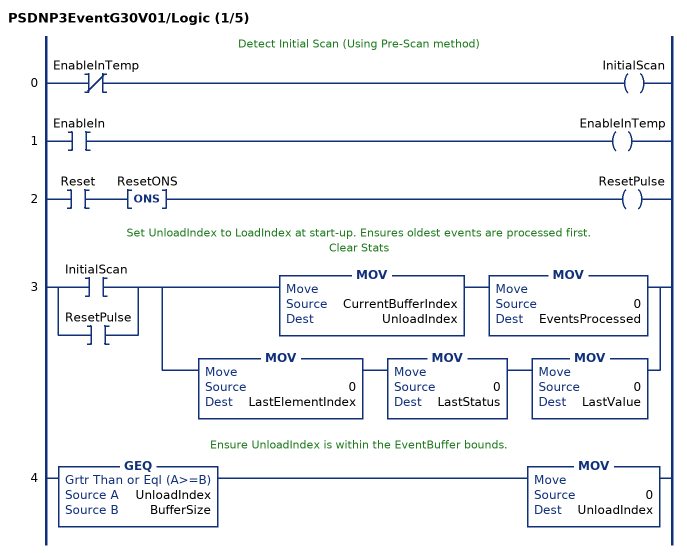
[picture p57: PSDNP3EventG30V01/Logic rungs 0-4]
   // Detect Initial Scan (Using Pre-Scan method)
   0: XIO(EnableInTemp)OTE(InitialScan);
   1: XIC(EnableIn)OTE(EnableInTemp);
   2: XIC(Reset)ONS(ResetONS)OTE(ResetPulse);
   // Set UnloadIndex to LoadIndex at start-up. Ensures oldest events are processed first.
   // Clear Stats
   3: [XIC(InitialScan) ,XIC(ResetPulse) ][MOV(CurrentBufferIndex,UnloadIndex) MOV(0,EventsProcessed) ,MOV(0,LastElementIndex) MOV(0,LastStatus) MOV(0,LastValue) ];
   // Ensure UnloadIndex is within the EventBuffer bounds.
   4: GEQ(UnloadIndex,BufferSize)MOV(0,UnloadIndex);
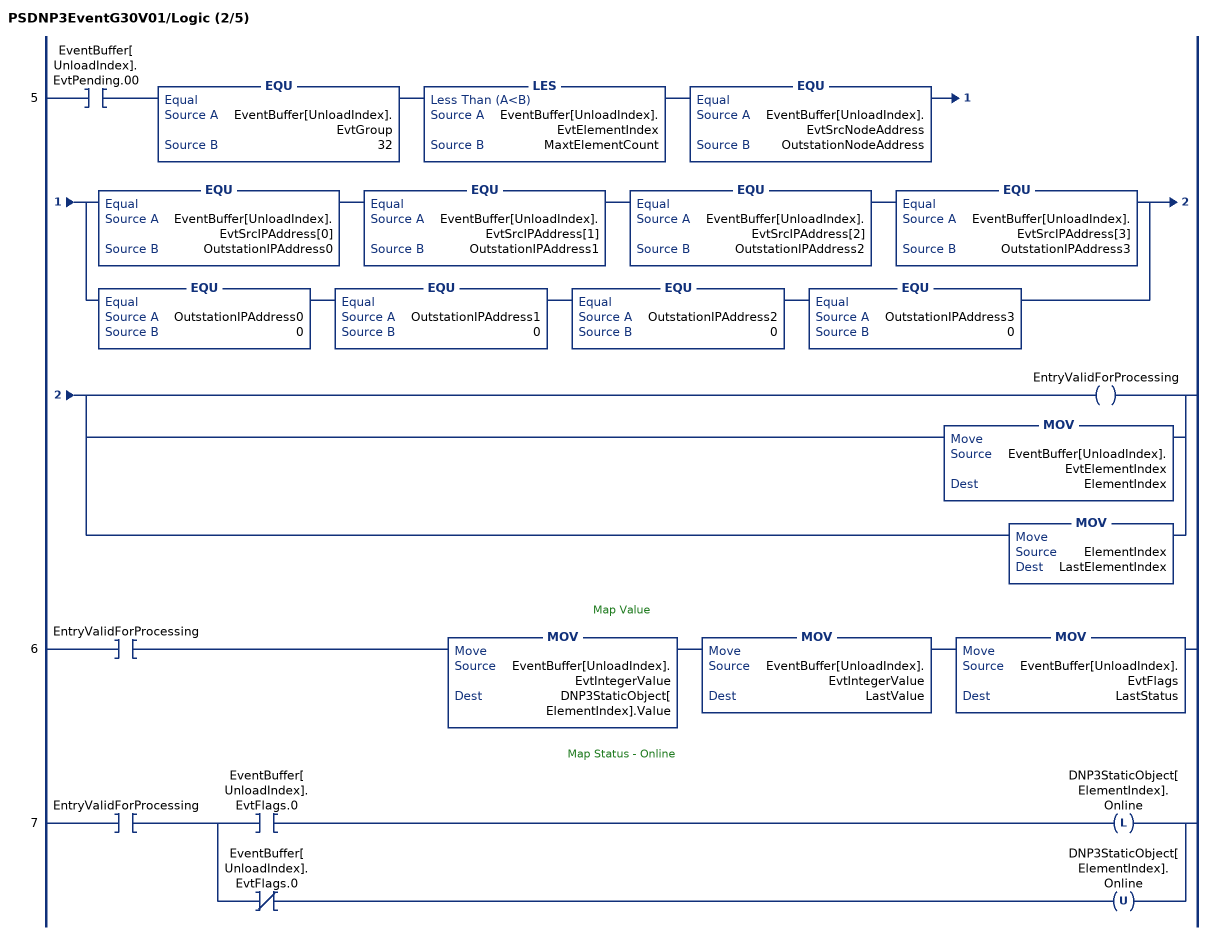
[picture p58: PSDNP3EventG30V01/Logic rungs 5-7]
   5: XIC(EventBuffer[UnloadIndex].EvtPending.00)EQU(EventBuffer[UnloadIndex].EvtGroup,32)LES(EventBuffer[UnloadIndex].EvtElementIndex,MaxtElementCount)EQU(EventBuffer[UnloadIndex].EvtSrcNodeAddress,OutstationNodeAddress)[EQU(EventBuffer[UnloadIndex].EvtSrcIPAddress[0],OutstationIPAddress0) EQU(EventBuffer[UnloadIndex].EvtSrcIPAddress[1],OutstationIPAddress1) EQU(EventBuffer[UnloadIndex].EvtSrcIPAddress[2],OutstationIPAddress2) EQU(EventBuffer[UnloadIndex].EvtSrcIPAddress[3],OutstationIPAddress3) ,EQU(OutstationIPAddress0,0) EQU(OutstationIPAddress1,0) EQU(OutstationIPAddress2,0) EQU(OutstationIPAddress3,0) ][OTE(EntryValidForProcessing) ,MOV(EventBuffer[UnloadIndex].EvtElementIndex,ElementIndex) ,MOV(ElementIndex,LastElementIndex) ];
   // Map Value
   6: XIC(EntryValidForProcessing)MOV(EventBuffer[UnloadIndex].EvtIntegerValue,DNP3StaticObject[ElementIndex].Value)MOV(EventBuffer[UnloadIndex].EvtIntegerValue,LastValue)MOV(EventBuffer[UnloadIndex].EvtFlags,LastStatus);
   // Map Status - Online
   7: XIC(EntryValidForProcessing)[XIC(EventBuffer[UnloadIndex].EvtFlags.0) OTL(DNP3StaticObject[ElementIndex].Online) ,XIO(EventBuffer[UnloadIndex].EvtFlags.0) OTU(DNP3StaticObject[ElementIndex].Online) ];
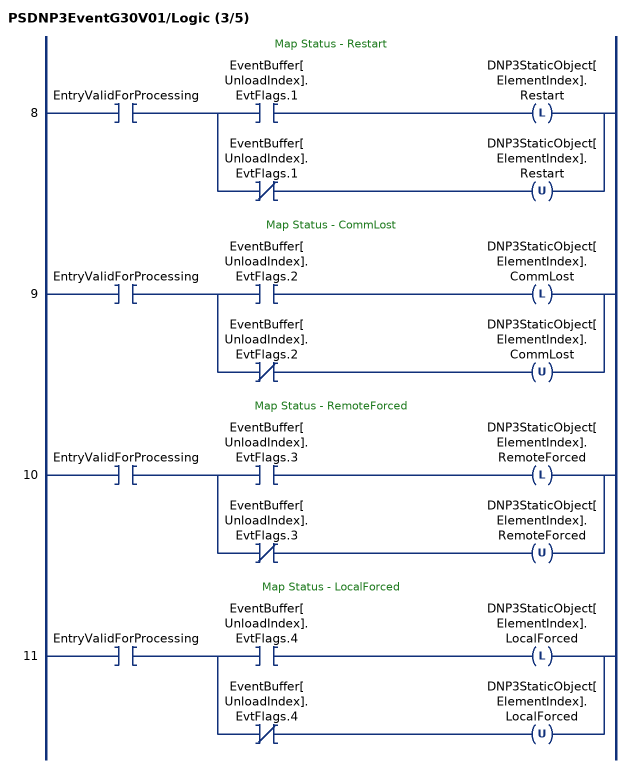
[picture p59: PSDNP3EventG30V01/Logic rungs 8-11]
   // Map Status - Restart
   8: XIC(EntryValidForProcessing)[XIC(EventBuffer[UnloadIndex].EvtFlags.1) OTL(DNP3StaticObject[ElementIndex].Restart) ,XIO(EventBuffer[UnloadIndex].EvtFlags.1) OTU(DNP3StaticObject[ElementIndex].Restart) ];
   // Map Status - CommLost
   9: XIC(EntryValidForProcessing)[XIC(EventBuffer[UnloadIndex].EvtFlags.2) OTL(DNP3StaticObject[ElementIndex].CommLost) ,XIO(EventBuffer[UnloadIndex].EvtFlags.2) OTU(DNP3StaticObject[ElementIndex].CommLost) ];
   // Map Status - RemoteForced
   10: XIC(EntryValidForProcessing)[XIC(EventBuffer[UnloadIndex].EvtFlags.3) OTL(DNP3StaticObject[ElementIndex].RemoteForced) ,XIO(EventBuffer[UnloadIndex].EvtFlags.3) OTU(DNP3StaticObject[ElementIndex].RemoteForced) ];
   // Map Status - LocalForced
   11: XIC(EntryValidForProcessing)[XIC(EventBuffer[UnloadIndex].EvtFlags.4) OTL(DNP3StaticObject[ElementIndex].LocalForced) ,XIO(EventBuffer[UnloadIndex].EvtFlags.4) OTU(DNP3StaticObject[ElementIndex].LocalForced) ];
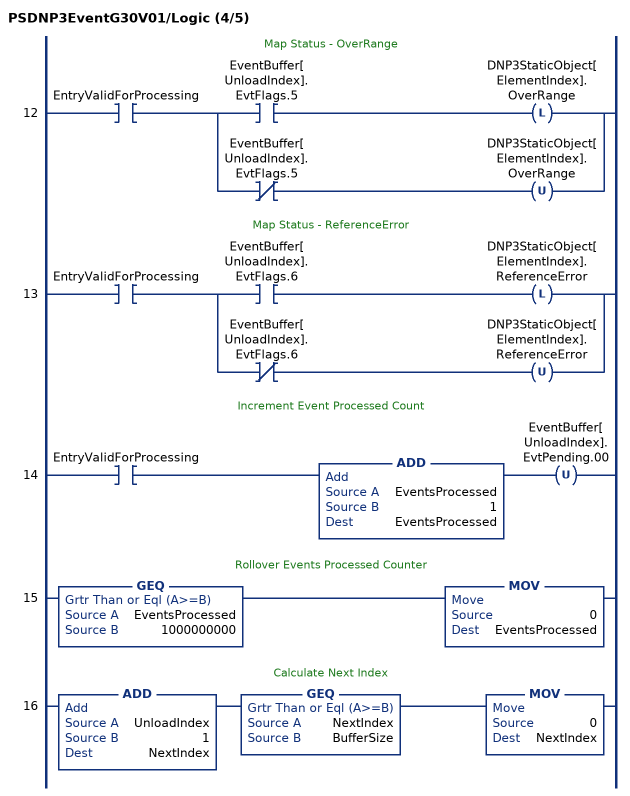
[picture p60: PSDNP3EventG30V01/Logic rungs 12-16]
   // Map Status - OverRange
   12: XIC(EntryValidForProcessing)[XIC(EventBuffer[UnloadIndex].EvtFlags.5) OTL(DNP3StaticObject[ElementIndex].OverRange) ,XIO(EventBuffer[UnloadIndex].EvtFlags.5) OTU(DNP3StaticObject[ElementIndex].OverRange) ];
   // Map Status - ReferenceError
   13: XIC(EntryValidForProcessing)[XIC(EventBuffer[UnloadIndex].EvtFlags.6) OTL(DNP3StaticObject[ElementIndex].ReferenceError) ,XIO(EventBuffer[UnloadIndex].EvtFlags.6) OTU(DNP3StaticObject[ElementIndex].ReferenceError) ];
   // Increment Event Processed Count
   14: XIC(EntryValidForProcessing)ADD(EventsProcessed,1,EventsProcessed)OTU(EventBuffer[UnloadIndex].EvtPending.00);
   // Rollover Events Processed Counter
   15: GEQ(EventsProcessed,1000000000)MOV(0,EventsProcessed);
   // Calculate Next Index
   16: ADD(UnloadIndex,1,NextIndex)GEQ(NextIndex,BufferSize)MOV(0,NextIndex);
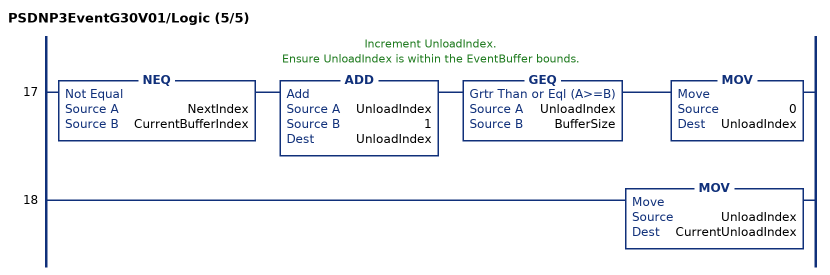
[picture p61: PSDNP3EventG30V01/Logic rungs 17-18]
   // Increment UnloadIndex.
   // Ensure UnloadIndex is within the EventBuffer bounds.
   17: NEQ(NextIndex,CurrentBufferIndex)ADD(UnloadIndex,1,UnloadIndex)GEQ(UnloadIndex,BufferSize)MOV(0,UnloadIndex);
   18: MOV(UnloadIndex,CurrentUnloadIndex);
END_ROUTINE
END_ADD_ON_INSTRUCTION
